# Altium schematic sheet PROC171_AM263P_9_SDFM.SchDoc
size 431 x 279 mm; Date: Not shown in title block; ApprovedBy: Not shown in title block; CheckedBy: Not shown in title block; Author: Not shown in title block; CompanyName: Not shown in title block; Engineer: Not shown in title block; Organization: Not shown in title block; Address1: Not shown in title block; Address2: Not shown in title block; Address3: Not shown in title block; Address4: Not shown in title block; DocumentNumber: 14; Revision: Use project parameter SCH_Rev; SheetNumber: 14; SheetTotal: 27; PageSetup: Record=PageOptions¦CenterHorizontal=True¦CenterVertical=True¦PrintScale=1.00¦XCorrection=1.00¦YCorrection=1.00¦PrintKind=0¦BorderSize=5000000¦LeftOffset=0¦BottomOffset=0¦Orientation=2¦PaperLength=1000¦PaperWidth=1000¦Scale=100¦PaperSource=15¦PrintQuality=600¦MediaType=1¦DitherType=10¦PaperKind=Letter¦PrintScaleMode=1
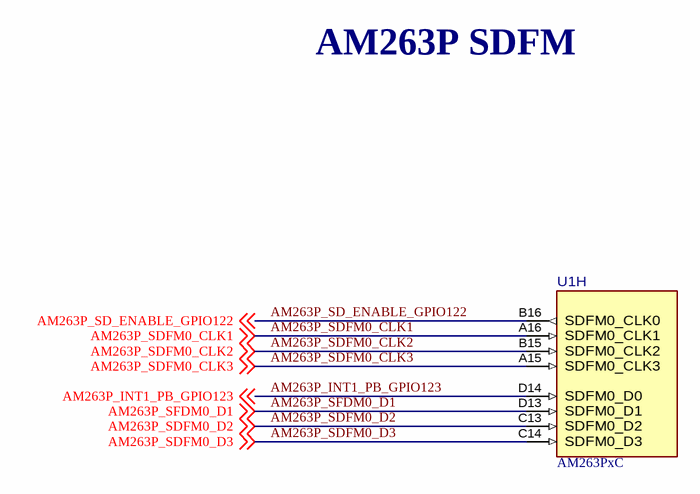
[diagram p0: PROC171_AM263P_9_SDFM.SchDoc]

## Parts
U1  AM263PxC  [ZCZ0324A-MFG]  (part H of 13)

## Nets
AM263P_INT1_PB_GPIO123: U1.D14(SDFM0_D0) ; off-sheet AM263P_INT1_PB_GPIO123
AM263P_SD_ENABLE_GPIO122: U1.B16(SDFM0_CLK0) ; off-sheet AM263P_SD_ENABLE_GPIO122
AM263P_SDFM0_CLK1: U1.A16(SDFM0_CLK1) ; off-sheet AM263P_SDFM0_CLK1
AM263P_SDFM0_CLK2: U1.B15(SDFM0_CLK2) ; off-sheet AM263P_SDFM0_CLK2
AM263P_SDFM0_CLK3: U1.A15(SDFM0_CLK3) ; off-sheet AM263P_SDFM0_CLK3
AM263P_SDFM0_D2: U1.C13(SDFM0_D2) ; off-sheet AM263P_SDFM0_D2
AM263P_SDFM0_D3: U1.C14(SDFM0_D3) ; off-sheet AM263P_SDFM0_D3
AM263P_SFDM0_D1: U1.D13(SDFM0_D1) ; off-sheet AM263P_SFDM0_D1

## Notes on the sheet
- AM263P SDFM

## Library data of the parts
U1 = CMP-0001698-2: Sitara™ Microcontroller; Manufacturer: Texas Instruments; SizeZ_mm: 1.4mm; Core Architecture: ARM Cortex-R5F; Data Bus Width: 32bits; Frequency_Fixed: 200MHz; Interface: I2C,SPI,UART,CAN,LIN,Ethernet,Other; Max Supply Voltage: 3.465V; Memory Size: 2MBytes; Memory Type: RAM; Min Supply Voltage: 1.14V; Number Of Cores: 1; Number Of I/Os: 140; Number Of I2C Channels: 4; Number Of Spi Channels: 5; Number Of Uart Channels: 6; Standoff Height: 0.35mm; AEC Category: Q200; CompType: IC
